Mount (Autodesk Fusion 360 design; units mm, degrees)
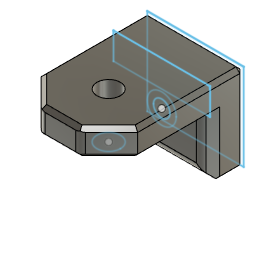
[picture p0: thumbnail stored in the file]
base_feature "Base Feature"
extrude "Extrude1" new body sketch "Reconstructed-Sketch1" + "Reconstructed-Sketch2" blind 7 bodies "Tube mount"
extrude "Extrude4" add sketch "Reconstructed-Sketch4" + "Reconstructed-Sketch2" blind 21
extrude "Extrude3" cut sketch "Reconstructed-Sketch3" + "Reconstructed-Sketch2" blind -3
extrude "Extrude2" cut sketch "Reconstructed-Sketch2" blind -7
extrude "Extrude5" cut sketch "Reconstructed-Sketch5" + "Reconstructed-Sketch2" blind -10
fillet "Fillet1" sketch "Reconstructed-Sketch2"
chamfer "Chamfer2" sketch "Reconstructed-Sketch2" distance 2
fillet "Fillet2" sketch "Reconstructed-Sketch2" radius 2
chamfer "Chamfer4" distance 6
chamfer "Chamfer5" sketch "Reconstructed-Sketch2" distance 0.8
fillet "Fillet3" sketch "Reconstructed-Sketch2" radius 2
named bodies: "Tube mount"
